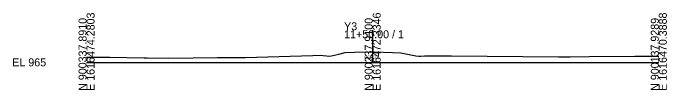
# Model space of a CAD drawing. Extents: x -26 to 203, y -10 to 2017.
# Drawn here: x -25.7 to 202.8, y 1490.3 to 1517.3 of the extents above; entities that cross this region are included whole.
import ezdxf

# ---------------------------------------------------------------- set-up
doc = ezdxf.new("R2010")
doc.units = 0
for name, color, linetype in [('Exist Cross Section Cell', 7, 'Continuous'), ('Exist XS Center Line Elevation Label', 7, 'Continuous'), ('Exist XS Ground Line', 7, 'Continuous')]:
    doc.layers.add(name, color=color, linetype=linetype)

msp = doc.modelspace()

# ---------------------------------------------------------------- linework, layer by layer
at = {"layer": 'Exist Cross Section Cell'}
for p, q in [((100, 1500), (100, 1511.26)), ((0, 1500), (100, 1500)), ((100, 1500), (200, 1500))]:
    msp.add_line(p, q, dxfattribs=at)
at = {"layer": 'Exist XS Ground Line'}
for p, q in [((100, 1503.74), (100.48, 1503.75)), ((100.48, 1503.75), (106.87, 1503.47)), ((0, 1501.78), (8.18, 1501.78)), ((8.18, 1501.78), (20.14, 1501.56)), ((20.14, 1501.56), (21.22, 1501.54)), ((21.22, 1501.54), (28.77, 1501.42)), ((28.77, 1501.42), (45.81, 1501.66)), ((45.81, 1501.66), (55.46, 1501.67)), ((55.46, 1501.67), (79.03, 1502.41)), ((79.03, 1502.41), (81.81, 1502.52)), ((81.81, 1502.52), (82.71, 1502.44)), ((82.71, 1502.44), (85.01, 1502.18)), ((85.01, 1502.18), (88.13, 1502.92)), ((88.13, 1502.92), (90.41, 1503.45)), ((90.41, 1503.45), (93.61, 1503.54)), ((93.61, 1503.54), (100, 1503.74)), ((106.87, 1503.47), (109.78, 1503.35)), ((109.78, 1503.35), (115.12, 1502.32)), ((115.12, 1502.32), (116.1, 1502.12)), ((116.1, 1502.12), (116.79, 1502.17)), ((116.79, 1502.17), (118.12, 1502.25)), ((118.12, 1502.25), (127.6, 1502.25)), ((127.6, 1502.25), (164.91, 1501.99)), ((164.91, 1501.99), (166, 1501.98)), ((166, 1501.98), (167.05, 1501.96)), ((167.05, 1501.96), (168.08, 1501.97)), ((168.08, 1501.97), (169.07, 1501.97)), ((169.07, 1501.97), (175.65, 1502.02)), ((175.65, 1502.02), (191.61, 1502.17)), ((191.61, 1502.17), (196.82, 1502.2)), ((196.82, 1502.2), (200, 1502.18))]:
    msp.add_line(p, q, dxfattribs=at)

# ---------------------------------------------------------------- texts
at = {"layer": 'Exist Cross Section Cell'}
for s, p in [('N 900337.8910', (0, 1490)), ('E 1616474.2803', (2.8, 1490)), ('N 900237.9100', (100, 1490)), ('E 1616472.3346', (102.8, 1490)), ('N 900137.9289', (200, 1490)), ('E 1616470.3888', (202.8, 1490))]:
    msp.add_text(s, height=2.8, rotation=90, dxfattribs=at).set_placement(p)
for s, p in [('Y3', (90, 1511.26)), ('11+50.00 / 1', (90, 1508.46)), ('EL 965', (-26, 1498.6))]:
    msp.add_text(s, height=2.8, dxfattribs=at).set_placement(p)
at = {"layer": 'Exist XS Center Line Elevation Label'}
msp.add_text('968.74', height=1.25, dxfattribs=at).set_placement((97.07, 1501.11))

doc.saveas('drawing.dxf')
